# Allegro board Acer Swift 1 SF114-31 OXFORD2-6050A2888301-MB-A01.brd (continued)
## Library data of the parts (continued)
C13 C7111 C7116 C7125 = CSC0402: part number: CSC0402-CSC0402_DY,CSC0402_DY,CSC_100X050X040_2,0.55MM,CSC0402,0402,,CSC0402_OPEN; signal model: C2_CSC0402_DY_CSC0402_DY; room: Sheet14
C14 C4504 C4505 = CSC0402: part number: CSC0402-0.1UF_16V_2,6010A0036403,CSC_100X050X040_2,0.55MM,CSC0402,0402,X7R,CAP-CHIP,0.1UF,16V,K,X7R,0402,TAP; signal model: C2_6010A0036403_0_1uF_16V_2; room: Sheet37
C18 = CSC0402: part number: CSC0402-22PF_50V_2,6010072202AT,CSC_100X050X040_2,0.55MM,CSC0402,0402,C0G,CAPACITOR-CHIP,22PF,50V,J,C0G,0402,TR; signal model: C2_6010072202AT_22pF_50V_2; room: Sheet18
C300-C306 C316 = CSC0402: part number: CSC0402-0.1UF_16V_2,6010A0036403,CSC_100X050X040_2,0.55MM,CSC0402,0402,X7R,CAP-CHIP,0.1UF,16V,K,X7R,0402,TAP; signal model: C2_6010A0036403_0_1uF_16V_2; room: Sheet17
C310 = CSC0402: part number: CSC0402-1UF_6.3V_2,6010B0006001,CSC_100X050X040_2,0.55MM,CSC0402,0402,X5R,CAP-CHIP,1UF,6.3V,K,X5R,0402,TR; signal model: C2_6010B0006001_1uF_6_3V_2; room: Sheet17
C312 = CSC0603: part number: CSC0603-10UF_6.3V_3_DY,6010B0044901_DY,CSC_160X080X080_2,0.95MM,CSC0603,0603,X5R,CAP-CHIP,10UF,6.3V,M,X5R,0603,TR; signal model: C2_6010B0044901_DY_10uF_6_3V_3_DY; room: Sheet17
C313 = CSC0603: part number: CSC0603-4.7UF_6.3V_3,6010B0009904,CSC_160X080X080_2,0.95MM,CSC0603,0603,X5R,CAP-CHIP,4.7UF,6.3V,K,X5R,0603,TR; signal model: C2_6010B0009904_4_7uF_6_3V_3; room: Sheet17
C351 = CSC0402: part number: CSC0402-CSC0402_DY,CSC0402_DY,CSC_100X050X040_2,0.55MM,CSC0402,0402,,CSC0402_OPEN; signal model: C2_CSC0402_DY_CSC0402_DY; room: Sheet17
C501 C508 C512 C513 C515 C517 C521 C530 C532 = CSC0603: part number: CSC0603-10UF_6.3V_3,6010B0044901,CSC_160X080X080_2,0.95MM,CSC0603,0603,X5R,CAP-CHIP,10UF,6.3V,M,X5R,0603,TR; signal model: C2_6010B0044901_10uF_6_3V_3; room: Sheet18
C502 = CSC0402: part number: CSC0402-2.2UF_6.3V_2,6010B0059301,CSC_100X050X040_2,0.55MM,CSC0402,0402,X5R,CAP-CHIP,2.2UF,6.3V,M,X5R,0402,TR; signal model: C2_6010B0059301_2_2uF_6_3V_2; room: Sheet18
C503 C511 = CSC0402: part number: CSC0402-1UF_6.3V_2,6010B0006001,CSC_100X050X040_2,0.55MM,CSC0402,0402,X5R,CAP-CHIP,1UF,6.3V,K,X5R,0402,TR; signal model: C2_6010B0006001_1uF_6_3V_2; room: Sheet18
C504 = CSC0603: part number: CSC0603-4.7UF_10V_3,6010B0067401,CSC_160X080X080_2,0.95MM,CSC0603,0603,X5R,CAP-CHIP,4.7UF,10V,K,X5R,0603,TR; signal model: C2_6010B0067401_4_7uF_10V_3; room: Sheet18
C505 C507 C509 C514 C516 C520 = CSC0402: part number: CSC0402-0.1UF_16V_2,6010A0036403,CSC_100X050X040_2,0.55MM,CSC0402,0402,X7R,CAP-CHIP,0.1UF,16V,K,X7R,0402,TAP; signal model: C2_6010A0036403_0_1uF_16V_2; room: Sheet18
C506 C523-C525 = CSC0402: part number: CSC0402-CSC0402_DY,CSC0402_DY,CSC_100X050X040_2,0.55MM,CSC0402,0402,,CSC0402_OPEN; signal model: C2_CSC0402_DY_CSC0402_DY; room: Sheet18
C510 = CSC0402: part number: CSC0402-22PF_50V_2_DY,6010072202AT_DY,CSC_100X050X040_2,0.55MM,CSC0402,0402,C0G,CAPACITOR-CHIP,22PF,50V,J,C0G,0402,TR; signal model: C2_6010072202AT_DY_22pF_50V_2_DY; room: Sheet18
C519 = CSC0402: part number: CSC0402-0.1UF_16V_2_DY,6010A0036403_DY,CSC_100X050X040_2,0.55MM,CSC0402,0402,X7R,CAP-CHIP,0.1UF,16V,K,X7R,0402,TAP; signal model: C2_6010A0036403_DY_0_1uF_16V_2_DY; room: Sheet18
C522 = CSC0603: part number: CSC0603-10UF_6.3V_3_DY,6010B0044901_DY,CSC_160X080X080_2,0.95MM,CSC0603,0603,X5R,CAP-CHIP,10UF,6.3V,M,X5R,0603,TR; signal model: C2_6010B0044901_DY_10uF_6_3V_3_DY; room: Sheet18
C531 = CSC0603: part number: CSC0603-4.7UF_6.3V_3,6010B0009904,CSC_160X080X080_2,0.95MM,CSC0603,0603,X5R,CAP-CHIP,4.7UF,6.3V,K,X5R,0603,TR; signal model: C2_6010B0009904_4_7uF_6_3V_3; room: Sheet18
C600 C601 = CSC0402: part number: CSC0402-470PF_50V_2_DY,6010A0025101_DY,CSC_100X050X040_2,0.55MM,CSC0402,0402,X7R,CAP-CHIP-471-K,50V-X7R-0402-TAP; signal model: C2_6010A0025101_DY_470pF_50V_2_DY; room: Sheet19
C602 C603 = CSC0603: part number: CSC0603-4.7UF_6.3V_3,6010B0009904,CSC_160X080X080_2,0.95MM,CSC0603,0603,X5R,CAP-CHIP,4.7UF,6.3V,K,X5R,0603,TR; signal model: C2_6010B0009904_4_7uF_6_3V_3; room: Sheet19
C604-C611 = CSC0402: part number: CSC0402-CSC0402_DY,CSC0402_DY,CSC_100X050X040_2,0.55MM,CSC0402,0402,,CSC0402_OPEN; signal model: C2_CSC0402_DY_CSC0402_DY; room: Sheet19
C900 C905 = CSC0603: part number: CSC0603-4.7UF_6.3V_3,6010B0009904,CSC_160X080X080_2,0.95MM,CSC0603,0603,X5R,CAP-CHIP,4.7UF,6.3V,K,X5R,0603,TR; signal model: C2_6010B0009904_4_7uF_6_3V_3; room: Sheet20
C901 C904 = CSC0402: part number: CSC0402-1UF_6.3V_2,6010B0006001,CSC_100X050X040_2,0.55MM,CSC0402,0402,X5R,CAP-CHIP,1UF,6.3V,K,X5R,0402,TR; signal model: C2_6010B0006001_1uF_6_3V_2; room: Sheet20
C902 = CSC0402: part number: CSC0402-0.1UF_16V_2_DY,6010A0036403_DY,CSC_100X050X040_2,0.55MM,CSC0402,0402,X7R,CAP-CHIP,0.1UF,16V,K,X7R,0402,TAP; signal model: C2_6010A0036403_DY_0_1uF_16V_2_DY; room: Sheet20
C903 C906 = CSC0402: part number: CSC0402-0.1UF_16V_2,6010A0036403,CSC_100X050X040_2,0.55MM,CSC0402,0402,X7R,CAP-CHIP,0.1UF,16V,K,X7R,0402,TAP; signal model: C2_6010A0036403_0_1uF_16V_2; room: Sheet20
C907 = CSC0402: part number: CSC0402-6.8PF_50V_2_DY,6010B0047803_DY,CSC_100X050X030_2,0.45MM,CSC0402,0402,C0G,CAPACITOR-CHIP,6.8PF,50V,D,C0G,0402,TR; signal model: C2_6010B0047803_6_8PF_50V_2_DY; room: Sheet20
C1301 C1303 = CSC0603: part number: CSC0603-10UF_6.3V_3,6010B0044901,CSC_160X080X080_2,0.95MM,CSC0603,0603,X5R,CAP-CHIP,10UF,6.3V,M,X5R,0603,TR; signal model: C2_6010B0044901_10uF_6_3V_3; room: Sheet21
C1302 C1304 = CSC0402: part number: CSC0402-0.1UF_16V_2,6010A0036403,CSC_100X050X040_2,0.55MM,CSC0402,0402,X7R,CAP-CHIP,0.1UF,16V,K,X7R,0402,TAP; signal model: C2_6010A0036403_0_1uF_16V_2; room: Sheet21
C1305-C1307 = CSC0402: part number: CSC0402-CSC0402_DY,CSC0402_DY,CSC_100X050X040_2,0.55MM,CSC0402,0402,,CSC0402_OPEN; signal model: C2_CSC0402_DY_CSC0402_DY; room: Sheet21
C2000 = CSC0805: part number: CSC0805-22UF_6.3V_5_DY,6010A0040702_DY,CSC_200X125X130_2,1.45MM,CSC0805,0805,X5R,CAP-CHIP-22UF-6.3V-M-X5R-0805-TAP; signal model: C2_6010A0040702_DY_22uF_6_3V_5_DY; room: Sheet22
C2001 = CSC0603: part number: CSC0603-2.2UF_6.3V_3,6010B0027401,CSC_160X080X090_2,1.05MM,CSC0603,0603,X5R,CAPACITOR-CHIP,2.2UF,6.3V,K,X5R,0603,TR; signal model: C2_6010B0027401_2_2uF_6_3V_3; room: Sheet22
C2002 = CSC0805: part number: CSC0805-22UF_6.3V_5,6010A0040702,CSC_200X125X130_2,1.45MM,CSC0805,0805,X5R,CAP-CHIP-22UF-6.3V-M-X5R-0805-TAP; signal model: C2_6010A0040702_22uF_6_3V_5; room: Sheet22
C2003 = CSC0402: part number: CSC0402-0.1UF_16V_2,6010A0036403,CSC_100X050X040_2,0.55MM,CSC0402,0402,X7R,CAP-CHIP,0.1UF,16V,K,X7R,0402,TAP; signal model: C2_6010A0036403_0_1uF_16V_2; room: Sheet22
C2004 = CSC0402: part number: CSC0402-CSC0402_DY,CSC0402_DY,CSC_100X050X040_2,0.55MM,CSC0402,0402,,CSC0402_OPEN; signal model: C2_CSC0402_DY_CSC0402_DY; room: Sheet22
C2005 = CAP_TANT: part number: CAP_TANT-100UF_6.3V_DY,6010A0052401_DY,CSTJB2_362X305X190_2,2.05MM,CAP_TANT,,,CAPACITOR-TANT-100UF-6.3V-M-85C-B2-ULESR-TAP; signal model: C2_6010A0052401_100uF_6_3V_DY; room: Sheet22
C2007 = CSC0805: part number: CSC0805-22UF_6.3V_5,6010A0040702,CSC_200X125X130_2,1.45MM,CSC0805,0805,X5R,CAP-CHIP-22UF-6.3V-M-X5R-0805-TAP; signal model: C2_6010A0040702_22uF_6_3V_5; room: Sheet47
C2426 = CSC0805: part number: CSC0805-22UF_6.3V_5,6010A0040702,CSC_200X125X130_2,1.45MM,CSC0805,0805,X5R,CAP-CHIP-22UF-6.3V-M-X5R-0805-TAP; signal model: C2_6010A0040702_22uF_6_3V_5; room: Sheet23
C2427 C2440 C2441 = CSC0402: part number: CSC0402-0.1UF_16V_2,6010A0036403,CSC_100X050X040_2,0.55MM,CSC0402,0402,X7R,CAP-CHIP,0.1UF,16V,K,X7R,0402,TAP; signal model: C2_6010A0036403_0_1uF_16V_2; room: Sheet23
C2428 = CAP_TANT: part number: CAP_TANT-100UF_6.3V_DY,6010A0052401_DY,CSTJB2_362X305X190_2,2.05MM,CAP_TANT,,,CAPACITOR-TANT-100UF-6.3V-M-85C-B2-ULESR-TAP; signal model: C2_6010A0052401_100uF_6_3V_DY; room: Sheet23
C2432 = CSC0402: part number: CSC0402-1000PF_50V_2,6010071020AT,CSC_100X050X055_2,0.7MM,CSC0402,0402,X7R,CAPACITOR-CHIP,1000PF,50V,K,X7R,0402,TR; signal model: C2_6010071020AT_1000PF_50V_2; room: Sheet23
C2456 = CSC0603: part number: CSC0603-2.2UF_6.3V_3,6010B0027401,CSC_160X080X090_2,1.05MM,CSC0603,0603,X5R,CAPACITOR-CHIP,2.2UF,6.3V,K,X5R,0603,TR; signal model: C2_6010B0027401_2_2uF_6_3V_3; room: Sheet23
C2457 = CSC0805: part number: CSC0805-47UF_6.3V_5_DY,6010B0096601_DY,CSC_200X125X130_2,1.45MM,CSC0805,0805,X5R,CAP-CHIP,47UF,6.3V,M,X5R,0805,TR; signal model: C2_6010B0096601_DY_47uF_6_3V_5_DY; room: Sheet23
C2460 C2462 = CSC0402: part number: CSC0402-0.1UF_16V_2,6010A0036403,CSC_100X050X040_2,0.55MM,CSC0402,0402,X7R,CAP-CHIP,0.1UF,16V,K,X7R,0402,TAP; signal model: C2_6010A0036403_0_1uF_16V_2; room: Sheet47
C2461 = CSC0402: part number: CSC0402-1000PF_50V_2,6010071020AT,CSC_100X050X055_2,0.7MM,CSC0402,0402,X7R,CAPACITOR-CHIP,1000PF,50V,K,X7R,0402,TR; signal model: C2_6010071020AT_1000PF_50V_2; room: Sheet47
C3000 = CSC0402: part number: CSC0402-0.01UF_50V_2,6010B0058401,CSC_100X050X040_2,0.55MM,CSC0402,0402,X7R,CAP-CHIP,0.01UF,50V,K,X7R,0402,TAP; signal model: C2_6010B0058401_0_01uF_50V_2; room: Sheet26
C3001 C3014 = CSC0402: part number: CSC0402-0.1UF_16V_2,6010A0036403,CSC_100X050X040_2,0.55MM,CSC0402,0402,X7R,CAP-CHIP,0.1UF,16V,K,X7R,0402,TAP; signal model: C2_6010A0036403_0_1uF_16V_2; room: Sheet26
C3002 = CSC0603: part number: CSC0603-10UF_6.3V_3,6010B0044901,CSC_160X080X080_2,0.95MM,CSC0603,0603,X5R,CAP-CHIP,10UF,6.3V,M,X5R,0603,TR; signal model: C2_6010B0044901_10uF_6_3V_3; room: Sheet26
C3003 = CSC0402: part number: CSC0402-680PF_50V_2,6010A0025501,CSC_100X050X040_2,0.55MM,CSC0402,0402,X7R,CAP-CHIP-681-K,50V-X7R-0402-TAP; signal model: C2_6010A0025501_680pF_50V_2; room: Sheet26
C3007 C3016 = CSC0402: part number: CSC0402-CSC0402_DY,CSC0402_DY,CSC_100X050X040_2,0.55MM,CSC0402,0402,,CSC0402_OPEN; signal model: C2_CSC0402_DY_CSC0402_DY; room: Sheet26
C3008 = CSC0402: part number: CSC0402-1000PF_50V_2,6010071020AT,CSC_100X050X055_2,0.7MM,CSC0402,0402,X7R,CAPACITOR-CHIP,1000PF,50V,K,X7R,0402,TR; signal model: C2_6010071020AT_1000PF_50V_2; room: Sheet26
C3009 = CSC0402: part number: CSC0402-0.1UF_16V_2_DY,6010A0036403_DY,CSC_100X050X040_2,0.55MM,CSC0402,0402,X7R,CAP-CHIP,0.1UF,16V,K,X7R,0402,TAP; signal model: C2_6010A0036403_DY_0_1uF_16V_2_DY; room: Sheet26
C3010 C3011 C4611-C4614 = CSC0402: part number: CSC0402-0.1UF_16V_2,6010A0036403,CSC_100X050X040_2,0.55MM,CSC0402,0402,X7R,CAP-CHIP,0.1UF,16V,K,X7R,0402,TAP; signal model: C2_6010A0036403_0_1uF_16V_2; room: Sheet36
C3015 = CSC0402: part number: CSC0402-0.047UF_16V_2_DY,6010B0046101_DY,CSC_100X050X040_2,0.55MM,CSC0402,0402,X7R,CAP-CHIP,0.047UF,16V,K,X7R,0402,TAP; signal model: C2_6010B0046101_0_047uF_16V_2_DY; room: Sheet26
C3019 = CSC0603: part number: CSC0603-4.7UF_25V_3,6010B0322201,CSC_160X080X095_2,1.10MM,CSC0603,0603,,CAPACITOR-CHIP,4.7UF,25V,K,X5R,0603,TR,0.8MM; signal model: C2_6010B0322201_4_7uF_25V_3; room: Sheet26
C3020 = CSC0402: part number: CSC0402-0.1UF_25V_2,6010B0087101,CSC_100X050X040_2,0.55MM,CSC0402,0402,X5R,CAP-CHIP,0.1UF,25V,K,X5R,0402,TR; signal model: C2_6010B0087101_0_1uF_25V_2; room: Sheet26
C3150 = CSC0402: part number: CSC0402-100PF_50V_2,6010071012AT,CSC_100X050X040_2,0.55MM,CSC0402,0402,NPO,CAP-CHIP-101-J,50V-NPO-0402; signal model: C2_6010071012AT_100pF_50V_2; room: Sheet27
C3151 = CSC0402: part number: CSC0402-22PF_50V_2_DY,6010072202AT_DY,CSC_100X050X040_2,0.55MM,CSC0402,0402,C0G,CAPACITOR-CHIP,22PF,50V,J,C0G,0402,TR; signal model: C2_6010072202AT_DY_22pF_50V_2_DY; room: Sheet27
C3160-C3167 = CSC0402: part number: CSC0402-0.1UF_16V_2,6010A0036403,CSC_100X050X040_2,0.55MM,CSC0402,0402,X7R,CAP-CHIP,0.1UF,16V,K,X7R,0402,TAP; signal model: C2_6010A0036403_0_1uF_16V_2; room: Sheet27
C3500 C3505 = CSC0603: part number: CSC0603-4.7UF_6.3V_3_DY,6010B0009904_DY,CSC_160X080X080_2,0.95MM,CSC0603,0603,X5R,CAP-CHIP,4.7UF,6.3V,K,X5R,0603,TR; signal model: C2_6010B0009904_DY_4_7uF_6_3V_3_DY; room: Sheet25
C3501-C3504 = CSC0402: part number: CSC0402-0.1UF_16V_2_DY,6010A0036403_DY,CSC_100X050X040_2,0.55MM,CSC0402,0402,X7R,CAP-CHIP,0.1UF,16V,K,X7R,0402,TAP; signal model: C2_6010A0036403_DY_0_1uF_16V_2_DY; room: Sheet25
C3950 C3951 C3954 C3955 = CSC0402: part number: CSC0402-2.2UF_6.3V_2,6010B0059301,CSC_100X050X040_2,0.55MM,CSC0402,0402,X5R,CAP-CHIP,2.2UF,6.3V,M,X5R,0402,TR; signal model: C2_6010B0059301_2_2uF_6_3V_2; room: Sheet24
C3952 C3953 C3956 C3957 C3959 = CSC0402: part number: CSC0402-0.1UF_16V_2,6010A0036403,CSC_100X050X040_2,0.55MM,CSC0402,0402,X7R,CAP-CHIP,0.1UF,16V,K,X7R,0402,TAP; signal model: C2_6010A0036403_0_1uF_16V_2; room: Sheet24
C3958 = CSC0402: part number: CSC0402-CSC0402_DY,CSC0402_DY,CSC_100X050X040_2,0.55MM,CSC0402,0402,,CSC0402_OPEN; signal model: C2_CSC0402_DY_CSC0402_DY; room: Sheet24
C3960 = CSC0402: part number: CSC0402-12PF_50V_2,6010A0036103,CSC_100X050X040_2,0.55MM,CSC0402,0402,NPO,CAP-CHIP-12PF-50V-J-NPO-0402-TAP; signal model: C2_6010A0036103_12pF_50V_2; room: Sheet24
C4100 C4101 C4107 C4143 C4144 C4150 C4151 C4158-C4160 = CSC0402: part number: CSC0402-0.22UF_6.3V_2,6010A0050701,CSC_100X050X040_2,0.55MM,CSC0402,0402,X5R,CAP-CHIP-0.22UF-M-6.3V-X5R-0402-TAP; signal model: C2_6010A0050701_0_22uF_6_3V_2; room: Sheet30
C4102 C4441 = CSC0402: part number: CSC0402-0.1UF_16V_2,6010A0036403,CSC_100X050X040_2,0.55MM,CSC0402,0402,X7R,CAP-CHIP,0.1UF,16V,K,X7R,0402,TAP; signal model: C2_6010A0036403_0_1uF_16V_2; room: Sheet30
C4103 C4110-C4112 C4251 C4252 = CSC0402: part number: CSC0402-0.1UF_16V_2,6010A0036403,CSC_100X050X040_2,0.55MM,CSC0402,0402,X7R,CAP-CHIP,0.1UF,16V,K,X7R,0402,TAP; signal model: C2_6010A0036403_0_1uF_16V_2; room: Sheet28
C4104-C4106 C4108 C4109 C4117-C4131 = CSC0402: part number: CSC0402-0.22UF_6.3V_2,6010A0050701,CSC_100X050X040_2,0.55MM,CSC0402,0402,X5R,CAP-CHIP-0.22UF-M-6.3V-X5R-0402-TAP; signal model: C2_6010A0050701_0_22uF_6_3V_2; room: Sheet28
C4113-C4116 = CSC0402: part number: CSC0402-0.1UF_16V_2,6010A0036403,CSC_100X050X040_2,0.55MM,CSC0402,0402,X7R,CAP-CHIP,0.1UF,16V,K,X7R,0402,TAP; signal model: C2_6010A0036403_0_1uF_16V_2; room: Sheet29
C4132 = CSC0402: part number: CSC0402-180PF_50V_2,6010B0045801,CSC_100X050X055_2,0.7MM,CSC0402,0402,NP0,CAPACITOR-CHIP,180PF,50V,J,NP0,0402,TR; signal model: C2_6010B0045801_180pF_50V_2; room: Sheet28
C4133-C4142 C4145-C4149 C4152-C4155 C4157 = CSC0402: part number: CSC0402-0.22UF_6.3V_2,6010A0050701,CSC_100X050X040_2,0.55MM,CSC0402,0402,X5R,CAP-CHIP-0.22UF-M-6.3V-X5R-0402-TAP; signal model: C2_6010A0050701_0_22uF_6_3V_2; room: Sheet29
C4156 = CSC0402: part number: CSC0402-180PF_50V_2,6010B0045801,CSC_100X050X055_2,0.7MM,CSC0402,0402,NP0,CAPACITOR-CHIP,180PF,50V,J,NP0,0402,TR; signal model: C2_6010B0045801_180pF_50V_2; room: Sheet29
C4163-C4167 C4169 = CSC0402: part number: CSC0402-0.1UF_10V_2,6010A0010501,CSC_100X050X040_2,0.55MM,CSC0402,0402,X7R,CAP-CHIP-104-J,10V-X7R-0402-TAP; signal model: C2_6010A0010501_0_1uF_10V_2; room: Sheet31
C4168 C4170-C4188 = CSC0402: part number: CSC0402-0.22UF_6.3V_2,6010A0050701,CSC_100X050X040_2,0.55MM,CSC0402,0402,X5R,CAP-CHIP-0.22UF-M-6.3V-X5R-0402-TAP; signal model: C2_6010A0050701_0_22uF_6_3V_2; room: Sheet31
C4189 = CSC0402: part number: CSC0402-180PF_50V_2,6010B0045801,CSC_100X050X055_2,0.7MM,CSC0402,0402,NP0,CAPACITOR-CHIP,180PF,50V,J,NP0,0402,TR; signal model: C2_6010B0045801_180pF_50V_2; room: Sheet31
C4190-C4193 = CSC0402: part number: CSC0402-0.1UF_10V_2,6010A0010501,CSC_100X050X040_2,0.55MM,CSC0402,0402,X7R,CAP-CHIP-104-J,10V-X7R-0402-TAP; signal model: C2_6010A0010501_0_1uF_10V_2; room: Sheet32
C4194-C4199 C4201-C4214 = CSC0402: part number: CSC0402-0.22UF_6.3V_2,6010A0050701,CSC_100X050X040_2,0.55MM,CSC0402,0402,X5R,CAP-CHIP-0.22UF-M-6.3V-X5R-0402-TAP; signal model: C2_6010A0050701_0_22uF_6_3V_2; room: Sheet32
C4200 = CSC0402: part number: CSC0402-0.1UF_10V_2,6010A0010501,CSC_100X050X040_2,0.55MM,CSC0402,0402,X7R,CAP-CHIP-104-J,10V-X7R-0402-TAP; signal model: C2_6010A0010501_0_1uF_10V_2; room: Sheet33
C4215 = CSC0402: part number: CSC0402-180PF_50V_2,6010B0045801,CSC_100X050X055_2,0.7MM,CSC0402,0402,NP0,CAPACITOR-CHIP,180PF,50V,J,NP0,0402,TR; signal model: C2_6010B0045801_180pF_50V_2; room: Sheet32
C4506 C4507 = CSC0402: part number: CSC0402-0.1UF_16V_2_DY,6010A0036403_DY,CSC_100X050X040_2,0.55MM,CSC0402,0402,X7R,CAP-CHIP,0.1UF,16V,K,X7R,0402,TAP; signal model: C2_6010A0036403_DY_0_1uF_16V_2_DY; room: Sheet38
C4509 C4510 = CSC0402: part number: CSC0402-12PF_50V_2,6010A0036103,CSC_100X050X040_2,0.55MM,CSC0402,0402,NPO,CAP-CHIP-12PF-50V-J-NPO-0402-TAP; signal model: C2_6010A0036103_12pF_50V_2; room: Sheet38
C4511 C4512 = CSC0402: part number: CSC0402-15PF_50V_2,6010071502AT,CSC_100X050X040_2,0.55MM,CSC0402,0402,NPO,CAP-CHIP,15PF,J-50V-NPO-0402-TAP; signal model: C2_6010071502AT_15pF_50V_2; room: Sheet40
C4513 = CSC0402: part number: CSC0402-0.1UF_16V_2,6010A0036403,CSC_100X050X040_2,0.55MM,CSC0402,0402,X7R,CAP-CHIP,0.1UF,16V,K,X7R,0402,TAP; signal model: C2_6010A0036403_0_1uF_16V_2; room: Sheet40
C4514 C4625 = CSC0402: part number: CSC0402-1UF_10V_2,6010B0055001,CSC_100X050X040_2,0.55MM,CSC0402,0402,X5R,CAP-CHIP,1UF,10V,K,X5R,0402,TR; signal model: C2_6010B0055001_1uF_10V_2; room: Sheet40
C4515 = CSC0402: part number: CSC0402-0.1UF_16V_2_DY,6010A0036403_DY,CSC_100X050X040_2,0.55MM,CSC0402,0402,X7R,CAP-CHIP,0.1UF,16V,K,X7R,0402,TAP; signal model: C2_6010A0036403_DY_0_1uF_16V_2_DY; room: Sheet40
C4516 C4525 C4526 C4564 C4565 C4609 C4630 = CSC0805: part number: CSC0805-22UF_6.3V_5,6010A0040702,CSC_200X125X130_2,1.45MM,CSC0805,0805,X5R,CAP-CHIP-22UF-6.3V-M-X5R-0805-TAP; signal model: C2_6010A0040702_22uF_6_3V_5; room: Sheet41
C4517-C4524 C4527-C4531 C4555 C4566 = CSC0402: part number: CSC0402-2.2UF_6.3V_2,6010B0059301,CSC_100X050X040_2,0.55MM,CSC0402,0402,X5R,CAP-CHIP,2.2UF,6.3V,M,X5R,0402,TR; signal model: C2_6010B0059301_2_2uF_6_3V_2; room: Sheet41
C4532-C4545 C4548-C4553 C4556-C4563 C4569 C4570 C4626 = CSC0402: part number: CSC0402-1UF_6.3V_2,6010B0006001,CSC_100X050X040_2,0.55MM,CSC0402,0402,X5R,CAP-CHIP,1UF,6.3V,K,X5R,0402,TR; signal model: C2_6010B0006001_1uF_6_3V_2; room: Sheet41
C4546 C4547 C4554 C4640 = CSC0603: part number: CSC0603-22UF_6.3V_3,6010B0219001,CSC_160X080X090_2,1.05MM,CSC0603,0603,,CAPACITOR-CHIP,22UF,6.3V,R6,0603,TR; signal model: C2_6010B0219001_22UF_6_3V_3; room: Sheet41
C4571 C4573 C4579-C4608 = CSC0402: part number: CSC0402-1UF_6.3V_2,6010B0006001,CSC_100X050X040_2,0.55MM,CSC0402,0402,X5R,CAP-CHIP,1UF,6.3V,K,X5R,0402,TR; signal model: C2_6010B0006001_1uF_6_3V_2; room: Sheet42
C4572 C4574-C4578 = CSC0603: part number: CSC0603-22UF_6.3V_3,6010B0219001,CSC_160X080X090_2,1.05MM,CSC0603,0603,,CAPACITOR-CHIP,22UF,6.3V,R6,0603,TR; signal model: C2_6010B0219001_22UF_6_3V_3; room: Sheet42
C4610 = CSC0402: part number: CSC0402-0.1UF_10V_2_DY,6010A0010501_DY,CSC_100X050X040_2,0.55MM,CSC0402,0402,X7R,CAP-CHIP-104-J,10V-X7R-0402-TAP; signal model: C2_6010A0010501_DY_0_1uF_10V_2_DY; room: Sheet35
C4616 = CSC0402: part number: CSC0402-0.2PF_50V_2,6010B0263501,CSC_100X050X055_2,0.70MM,CSC0402,0402,NP0,CAPACITOR-CHIP,0.2PF,50V,B,NP0,0402,TR; signal model: C2_6010B0263501_0_2pF_50V_2; room: Sheet34
C4617 = CSC0402: part number: CSC0402-0.1UF_10V_2_DY,6010A0010501_DY,CSC_100X050X040_2,0.55MM,CSC0402,0402,X7R,CAP-CHIP-104-J,10V-X7R-0402-TAP; signal model: C2_6010A0010501_DY_0_1uF_10V_2_DY; room: Sheet34
C4623 = CSC0402: part number: CSC0402-0.2PF_50V_2,6010B0263501,CSC_100X050X055_2,0.70MM,CSC0402,0402,NP0,CAPACITOR-CHIP,0.2PF,50V,B,NP0,0402,TR; signal model: C2_6010B0263501_0_2pF_50V_2; room: Sheet35
C4627 = CSC0805: part number: CSC0805-CSC0805_DY,CSC0805_DY,CSC_200X125X130_2,1.45MM,CSC0805,0805,,CSC0805_OPEN; signal model: C2_CSC0805_DY_CSC0805_DY; room: Sheet40
C4631 C4636 = CSC0402: part number: CSC0402-0.1UF_16V_2,6010A0036403,CSC_100X050X040_2,0.55MM,CSC0402,0402,X7R,CAP-CHIP,0.1UF,16V,K,X7R,0402,TAP; signal model: C2_6010A0036403_0_1uF_16V_2; room: Sheet38
C4652 = CSC0402: part number: CSC0402-CSC0402_DY,CSC0402_DY,CSC_100X050X040_2,0.55MM,CSC0402,0402,,CSC0402_OPEN; signal model: C2_CSC0402_DY_CSC0402_DY; room: Sheet37
C6000 C6010 = CSC0805: part number: CSC0805-10UF_25V_5,6010B0150801,CSC_200X125X140_2,1.55MM,CSC0805,0805,X5R,CAP-CHIP,10UF,25V,K,X5R,0805,TR,1.25MM; signal model: C2_6010B0150801_10UF_25V_5; room: Sheet5
C6001 C6011 = CSC0805: part number: CSC0805-4.7UF_25V_5,6010B0048901,CSC_200X125X130_2,1.45MM,CSC0805,0805,X5R,CAP-CHIP,4.7UF,25V,K,X5R,0805,TR; signal model: C2_6010B0048901_4_7uF_25V_5; room: Sheet5
C6020 C6023 C6032 = CSC0402: part number: CSC0402-0.1UF_16V_2,6010A0036403,CSC_100X050X040_2,0.55MM,CSC0402,0402,X7R,CAP-CHIP,0.1UF,16V,K,X7R,0402,TAP; signal model: C2_6010A0036403_0_1uF_16V_2; room: Sheet5
C6021 C6022 C6024 C6025 C6031 = CSC0603: part number: CSC0603-0.1UF_25V_3,6010A0057701,CSC_160X080X080_2,0.95MM,CSC0603,0603,X7R,CAP-CHIP,0.1UF,25V,K,X7R,0603,TR; signal model: C2_6010A0057701_0_1uF_25V_3; room: Sheet5
C6026 = CSC0603: part number: CSC0603-1UF_25V_3,6010B0067601,CSC_160X080X080_2,0.95MM,CSC0603,0603,X5R,CAP-CHIP,1UF,25V,K,X5R,0603,TR; signal model: C2_6010B0067601_1uF_25V_3; room: Sheet5
C6027 = CSC0402: part number: CSC0402-0.047UF_16V_2,6010B0046101,CSC_100X050X040_2,0.55MM,CSC0402,0402,X7R,CAP-CHIP,0.047UF,16V,K,X7R,0402,TAP; signal model: C2_6010B0046101_0_047uF_16V_2; room: Sheet5
C6028 C6051 = CSC0402: part number: CSC0402-1UF_10V_2,6010B0055001,CSC_100X050X040_2,0.55MM,CSC0402,0402,X5R,CAP-CHIP,1UF,10V,K,X5R,0402,TR; signal model: C2_6010B0055001_1uF_10V_2; room: Sheet5
C6030 C7604 = CSC0402: part number: CSC0402-470PF_50V_2,6010A0025101,CSC_100X050X040_2,0.55MM,CSC0402,0402,X7R,CAP-CHIP-471-K,50V-X7R-0402-TAP; signal model: C2_6010A0025101_470pF_50V_2; room: Sheet5
C6033 = CSC0603: part number: CSC0603-0.1UF_25V_3_DY,6010A0057701_DY,CSC_160X080X080_2,0.95MM,CSC0603,0603,X7R,CAP-CHIP,0.1UF,25V,K,X7R,0603,TR; signal model: C2_6010A0057701_0_1uF_25V_3_DY; room: Sheet5
C6036 C6037 = CSC0402: part number: CSC0402-100PF_50V_2,6010071012AT,CSC_100X050X040_2,0.55MM,CSC0402,0402,NPO,CAP-CHIP-101-J,50V-NPO-0402; signal model: C2_6010071012AT_100pF_50V_2; room: Sheet5
C6050 C7601 = CSC0402: part number: CSC0402-1000PF_50V_2,6010071020AT,CSC_100X050X055_2,0.7MM,CSC0402,0402,X7R,CAPACITOR-CHIP,1000PF,50V,K,X7R,0402,TR; signal model: C2_6010071020AT_1000PF_50V_2; room: Sheet5
C6100 C6150 = CAP_AL_SP: part number: CAP_AL_SP-100UF_6.3V,6010B0228101,CS_730X430X210_2,2.25MM,CAP_AL_SP,,,CAPACITOR-AL-SP,100UF,6.3V,M,-40~+105C,DX1.9,SMD,TR,17MOHM; signal model: C2_6010B0228101_100uF_6_3V; room: Sheet6
C6109 C6115 C6165 C6169 = CSC0402: part number: CSC0402-0.1UF_16V_2,6010A0036403,CSC_100X050X040_2,0.55MM,CSC0402,0402,X7R,CAP-CHIP,0.1UF,16V,K,X7R,0402,TAP; signal model: C2_6010A0036403_0_1uF_16V_2; room: Sheet6
C6110 C6160 C6161 = CSC0805: part number: CSC0805-10UF_25V_5,6010B0150801,CSC_200X125X140_2,1.55MM,CSC0805,0805,X5R,CAP-CHIP,10UF,25V,K,X5R,0805,TR,1.25MM; signal model: C2_6010B0150801_10UF_25V_5; room: Sheet6
C6111 = CSC0805: part number: CSC0805-4.7UF_25V_5,6010B0048901,CSC_200X125X130_2,1.45MM,CSC0805,0805,X5R,CAP-CHIP,4.7UF,25V,K,X5R,0805,TR; signal model: C2_6010B0048901_4_7uF_25V_5; room: Sheet6
C6121 = CSC0603: part number: CSC0603-10UF_6.3V_3,6010B0044901,CSC_160X080X080_2,0.95MM,CSC0603,0603,X5R,CAP-CHIP,10UF,6.3V,M,X5R,0603,TR; signal model: C2_6010B0044901_10uF_6_3V_3; room: Sheet6
C6122 C6172 = CSC0402: part number: CSC0402-1UF_6.3V_2,6010B0006001,CSC_100X050X040_2,0.55MM,CSC0402,0402,X5R,CAP-CHIP,1UF,6.3V,K,X5R,0402,TR; signal model: C2_6010B0006001_1uF_6_3V_2; room: Sheet6
C6162 = CSC0805: part number: CSC0805-10UF_25V_5_DY,6010B0150801_DY,CSC_200X125X140_2,1.55MM,CSC0805,0805,X5R,CAP-CHIP,10UF,25V,K,X5R,0805,TR,1.25MM; signal model: C2_6010B0150801_10UF_25V_5_DY; room: Sheet6
C6166 = CSC0402: part number: CSC0402-CSC0402_DY,CSC0402_DY,CSC_100X050X040_2,0.55MM,CSC0402,0402,,CSC0402_OPEN; signal model: C2_CSC0402_DY_CSC0402_DY; room: Sheet6
C6600-C6608 = CSC0805: part number: CSC0805-22UF_6.3V_5,6010A0040702,CSC_200X125X130_2,1.45MM,CSC0805,0805,X5R,CAP-CHIP-22UF-6.3V-M-X5R-0805-TAP; signal model: C2_6010A0040702_22uF_6_3V_5; room: Sheet9
C6609 = CAP_AL_SP: part number: CAP_AL_SP-220UF_2V_10%,6010B0216001,CS_730X430X210_2,2.25MM,CAP_AL_SP,,,CAPACITOR-AL-SP,220UF,2V,-35%/+10%,105C,DX1.9,SMD,TR,9MOHM; signal model: C2_6010B0216001_220uF_2V_10%; room: Sheet9
C6610 C6611 = CSC0805: part number: CSC0805-10UF_25V_5,6010B0150801,CSC_200X125X140_2,1.55MM,CSC0805,0805,X5R,CAP-CHIP,10UF,25V,K,X5R,0805,TR,1.25MM; signal model: C2_6010B0150801_10UF_25V_5; room: Sheet9
C6612 = CSC0402: part number: CSC0402-0.1UF_25V_2,6010B0087101,CSC_100X050X040_2,0.55MM,CSC0402,0402,X5R,CAP-CHIP,0.1UF,25V,K,X5R,0402,TR; signal model: C2_6010B0087101_0_1uF_25V_2; room: Sheet9
C6613 = CSC0402: part number: CSC0402-330PF_50V_2,6010A0010301,CSC_100X050X040_2,0.55MM,CSC0402,0402,X7R,CAP-CHIP-331-J,50V-X7R-0402-TAP; signal model: C2_6010A0010301_330pF_50V_2; room: Sheet8
C6614 = CSC0402: part number: CSC0402-10PF_50V_2,6010A0025401,CSC_100X050X040_2,0.55MM,CSC0402,0402,NPO,CAP-CHIP-10PF-D,50V-NPO-0402-TAP; signal model: C2_6010A0025401_10pF_50V_2; room: Sheet8
C6615 = CSC0402: part number: CSC0402-0.22UF_16V_2,6010B0150901,CSC_100X050X055_2,0.7MM,CSC0402,0402,X7R,CAPACITOR-CHIP,0.22UF,16V,K,X7R,0402,TR,0.5MM; signal model: C2_6010B0150901_0_22uF_16V_2; room: Sheet8
C6616 C6618 = CSC0402: part number: CSC0402-1000PF_50V_2,6010071020AT,CSC_100X050X055_2,0.7MM,CSC0402,0402,X7R,CAPACITOR-CHIP,1000PF,50V,K,X7R,0402,TR; signal model: C2_6010071020AT_1000PF_50V_2; room: Sheet8
C6617 = CSC0402: part number: CSC0402-4700PF_50V_2,6010A0029301,CSC_100X050X040_2,0.55MM,CSC0402,0402,X7R,CAP-CHIP-472-K,50V-X7R-0402-TAP; signal model: C2_6010A0029301_4700pF_50V_2; room: Sheet8
C6639 = CSC0402: part number: CSC0402-CSC0402_DY,CSC0402_DY,CSC_100X050X040_2,0.55MM,CSC0402,0402,,CSC0402_OPEN; signal model: C2_CSC0402_DY_CSC0402_DY; room: Sheet8
C6640 = CSC0402: part number: CSC0402-1.2PF_50V_2,6010B0077201,CSC_100X050X040_2,0.55MM,CSC0402,0402,C0G,CAP-CHIP,1.2PF,50V,B,C0G,0402,TR; signal model: C2_6010B0077201_1_2pF_50V_2; room: Sheet8
C6642 = CSC0402: part number: CSC0402-1UF_6.3V_2,6010B0006001,CSC_100X050X040_2,0.55MM,CSC0402,0402,X5R,CAP-CHIP,1UF,6.3V,K,X5R,0402,TR; signal model: C2_6010B0006001_1uF_6_3V_2; room: Sheet8
C6643 = CSC0603: part number: CSC0603-2.2UF_6.3V_3,6010B0027401,CSC_160X080X090_2,1.05MM,CSC0603,0603,X5R,CAPACITOR-CHIP,2.2UF,6.3V,K,X5R,0603,TR; signal model: C2_6010B0027401_2_2uF_6_3V_3; room: Sheet8
C6645 = CSC0402: part number: CSC0402-470PF_50V_2,6010A0025101,CSC_100X050X040_2,0.55MM,CSC0402,0402,X7R,CAP-CHIP-471-K,50V-X7R-0402-TAP; signal model: C2_6010A0025101_470pF_50V_2; room: Sheet8
C6646 C6647 = CSC0402: part number: CSC0402-0.01UF_50V_2,6010B0058401,CSC_100X050X040_2,0.55MM,CSC0402,0402,X7R,CAP-CHIP,0.01UF,50V,K,X7R,0402,TAP; signal model: C2_6010B0058401_0_01uF_50V_2; room: Sheet8
C6649 = CSC0402: part number: CSC0402-2200PF_50V_2,6010A0036305,CSC_100X050X040_2,0.55MM,CSC0402,0402,X7R,CAP-CHIP-2200PF-50V-K-X7R-0402-TAP; signal model: C2_6010A0036305_2200pF_50V_2; room: Sheet8
C6699 = CAP_AL_SP: part number: CAP_AL_SP-15UF_25V_DY,6010B0217801_DY,CS_730X430X210_2_615,2.25MM,CAP_AL_SP,,,CAPACITOR-AL-SP,15UF,25V,M,105C,DX1.9,TR,70MOHM; signal model: C2_6010B0217801_DY_15uF_25V_DY; room: Sheet9
C6700 C6701 = CSC0805: part number: CSC0805-22UF_6.3V_5,6010A0040702,CSC_200X125X130_2,1.45MM,CSC0805,0805,X5R,CAP-CHIP-22UF-6.3V-M-X5R-0805-TAP; signal model: C2_6010A0040702_22uF_6_3V_5; room: Sheet11
C6702 = CAP_AL_SP: part number: CAP_AL_SP-220UF_2V_10%,6010B0216001,CS_730X430X210_2,2.25MM,CAP_AL_SP,,,CAPACITOR-AL-SP,220UF,2V,-35%/+10%,105C,DX1.9,SMD,TR,9MOHM; signal model: C2_6010B0216001_220uF_2V_10%; room: Sheet11
C6710 C6711 = CSC0805: part number: CSC0805-10UF_25V_5,6010B0150801,CSC_200X125X140_2,1.55MM,CSC0805,0805,X5R,CAP-CHIP,10UF,25V,K,X5R,0805,TR,1.25MM; signal model: C2_6010B0150801_10UF_25V_5; room: Sheet11
C6712 = CSC0402: part number: CSC0402-0.1UF_25V_2,6010B0087101,CSC_100X050X040_2,0.55MM,CSC0402,0402,X5R,CAP-CHIP,0.1UF,25V,K,X5R,0402,TR; signal model: C2_6010B0087101_0_1uF_25V_2; room: Sheet11
C6713 = CSC0402: part number: CSC0402-330PF_50V_2,6010A0010301,CSC_100X050X040_2,0.55MM,CSC0402,0402,X7R,CAP-CHIP-331-J,50V-X7R-0402-TAP; signal model: C2_6010A0010301_330pF_50V_2; room: Sheet10
C6714 = CSC0402: part number: CSC0402-10PF_50V_2,6010A0025401,CSC_100X050X040_2,0.55MM,CSC0402,0402,NPO,CAP-CHIP-10PF-D,50V-NPO-0402-TAP; signal model: C2_6010A0025401_10pF_50V_2; room: Sheet10
C6715 = CSC0402: part number: CSC0402-0.22UF_16V_2,6010B0150901,CSC_100X050X055_2,0.7MM,CSC0402,0402,X7R,CAPACITOR-CHIP,0.22UF,16V,K,X7R,0402,TR,0.5MM; signal model: C2_6010B0150901_0_22uF_16V_2; room: Sheet10
C6716 C6718 = CSC0402: part number: CSC0402-1000PF_50V_2,6010071020AT,CSC_100X050X055_2,0.7MM,CSC0402,0402,X7R,CAPACITOR-CHIP,1000PF,50V,K,X7R,0402,TR; signal model: C2_6010071020AT_1000PF_50V_2; room: Sheet10
C6717 = CSC0402: part number: CSC0402-4700PF_50V_2,6010A0029301,CSC_100X050X040_2,0.55MM,CSC0402,0402,X7R,CAP-CHIP-472-K,50V-X7R-0402-TAP; signal model: C2_6010A0029301_4700pF_50V_2; room: Sheet10
C6739 = CSC0402: part number: CSC0402-CSC0402_DY,CSC0402_DY,CSC_100X050X040_2,0.55MM,CSC0402,0402,,CSC0402_OPEN; signal model: C2_CSC0402_DY_CSC0402_DY; room: Sheet10
C6740 = CSC0402: part number: CSC0402-1.2PF_50V_2,6010B0077201,CSC_100X050X040_2,0.55MM,CSC0402,0402,C0G,CAP-CHIP,1.2PF,50V,B,C0G,0402,TR; signal model: C2_6010B0077201_1_2pF_50V_2; room: Sheet10
C6742 = CSC0402: part number: CSC0402-1UF_6.3V_2,6010B0006001,CSC_100X050X040_2,0.55MM,CSC0402,0402,X5R,CAP-CHIP,1UF,6.3V,K,X5R,0402,TR; signal model: C2_6010B0006001_1uF_6_3V_2; room: Sheet10
C6743 = CSC0603: part number: CSC0603-2.2UF_6.3V_3,6010B0027401,CSC_160X080X090_2,1.05MM,CSC0603,0603,X5R,CAPACITOR-CHIP,2.2UF,6.3V,K,X5R,0603,TR; signal model: C2_6010B0027401_2_2uF_6_3V_3; room: Sheet10
C6745 = CSC0402: part number: CSC0402-470PF_50V_2,6010A0025101,CSC_100X050X040_2,0.55MM,CSC0402,0402,X7R,CAP-CHIP-471-K,50V-X7R-0402-TAP; signal model: C2_6010A0025101_470pF_50V_2; room: Sheet10
C6746 C6747 = CSC0402: part number: CSC0402-0.01UF_50V_2,6010B0058401,CSC_100X050X040_2,0.55MM,CSC0402,0402,X7R,CAP-CHIP,0.01UF,50V,K,X7R,0402,TAP; signal model: C2_6010B0058401_0_01uF_50V_2; room: Sheet10
C6749 = CSC0402: part number: CSC0402-2200PF_50V_2,6010A0036305,CSC_100X050X040_2,0.55MM,CSC0402,0402,X7R,CAP-CHIP-2200PF-50V-K-X7R-0402-TAP; signal model: C2_6010A0036305_2200pF_50V_2; room: Sheet10
C7000 C7002 C60610-C60612 C60910-C60912 C61010 C61110 C61700 C61710 = CSC0603: part number: CSC0603-10UF_6.3V_3,6010B0044901,CSC_160X080X080_2,0.95MM,CSC0603,0603,X5R,CAP-CHIP,10UF,6.3V,M,X5R,0603,TR; signal model: C2_6010B0044901_10uF_6_3V_3; room: Sheet12
C7001 C7003 C60600-C60604 C60901 C61000 C61100 = CSC0805: part number: CSC0805-22UF_6.3V_5,6010A0040702,CSC_200X125X130_2,1.45MM,CSC0805,0805,X5R,CAP-CHIP-22UF-6.3V-M-X5R-0805-TAP; signal model: C2_6010A0040702_22uF_6_3V_5; room: Sheet12
C7100 = CSC0402: part number: CSC0402-220PF_50V_2,6010B0076701,CSC_100X050X040_2,0.55MM,CSC0402,0402,C0G,CAP-CHIP,220PF,50V,J,C0G,0402,TR; signal model: C2_6010B0076701_220pF_50V_2; room: Sheet14
C7101 C7109 = CSC0402: part number: CSC0402-33PF_50V_2,6010A0028901,CSC_100X050X040_2,0.56MM,CSC0402,0402,,CAP-CHIP-33PF-J,50V-TAP(0402); signal model: C2_6010A0028901_33pF_50V_2; room: Sheet14
C7102 = CSC0805: part number: CSC0805-10UF_6.3V_5,6010A0032901,CSC_200X125X130_2,1.45MM,CSC0805,0805,X5R,CAP-CHIP-106-K,6.3V-X5R-0805-TAP; signal model: C2_6010A0032901_10uF_6_3V_5; room: Sheet14
C7104 C7108 C7121 = CSC0603: part number: CSC0603-10UF_6.3V_3,6010B0044901,CSC_160X080X080_2,0.95MM,CSC0603,0603,X5R,CAP-CHIP,10UF,6.3V,M,X5R,0603,TR; signal model: C2_6010B0044901_10uF_6_3V_3; room: Sheet14
C7110 C7114 C7120 C7123 = CSC0402: part number: CSC0402-1UF_10V_2,6010B0055001,CSC_100X050X040_2,0.55MM,CSC0402,0402,X5R,CAP-CHIP,1UF,10V,K,X5R,0402,TR; signal model: C2_6010B0055001_1uF_10V_2; room: Sheet14
C7122 = CSC0402: part number: CSC0402-680PF_50V_2,6010A0025501,CSC_100X050X040_2,0.55MM,CSC0402,0402,X7R,CAP-CHIP-681-K,50V-X7R-0402-TAP; signal model: C2_6010A0025501_680pF_50V_2; room: Sheet14
C7203 C7205 = CSC0402: part number: CSC0402-0.1UF_16V_2_DY,6010A0036403_DY,CSC_100X050X040_2,0.55MM,CSC0402,0402,X7R,CAP-CHIP,0.1UF,16V,K,X7R,0402,TAP; signal model: C2_6010A0036403_DY_0_1uF_16V_2_DY; room: Sheet13
C7206 = CSC0402: part number: CSC0402-0.1UF_16V_2,6010A0036403,CSC_100X050X040_2,0.55MM,CSC0402,0402,X7R,CAP-CHIP,0.1UF,16V,K,X7R,0402,TAP; signal model: C2_6010A0036403_0_1uF_16V_2; room: Sheet13
C7207 C7225 = CSC0402: part number: CSC0402-CSC0402_DY,CSC0402_DY,CSC_100X050X040_2,0.55MM,CSC0402,0402,,CSC0402_OPEN; signal model: C2_CSC0402_DY_CSC0402_DY; room: Sheet13
C7510-C7513 C7541 C7546 C7577 = CSC0402: part number: CSC0402-0.1UF_25V_2,6010B0087101,CSC_100X050X040_2,0.55MM,CSC0402,0402,X5R,CAP-CHIP,0.1UF,25V,K,X5R,0402,TR; signal model: C2_6010B0087101_0_1uF_25V_2; room: Sheet46
C7514-C7522 C7526 C7527 C7551 C7552 C7566-C7569 C7572-C7574 C7591 C7593 = CSC0402: part number: CSC0402-0.1UF_16V_2,6010A0036403,CSC_100X050X040_2,0.55MM,CSC0402,0402,X7R,CAP-CHIP,0.1UF,16V,K,X7R,0402,TAP; signal model: C2_6010A0036403_0_1uF_16V_2; room: Sheet46
C7528 C7529 C7531-C7534 = CSC0402: part number: CSC0402-18PF_50V_2,6010A0036105,CSC_100X050X040_2,0.55MM,CSC0402,0402,NPO,CAP-CHIP-18PF-50V-J-NPO-0402-TAP; signal model: C2_6010A0036105_18pF_50V_2; room: Sheet31
C7535-C7540 = CSC0402: part number: CSC0402-18PF_50V_2,6010A0036105,CSC_100X050X040_2,0.55MM,CSC0402,0402,NPO,CAP-CHIP-18PF-50V-J-NPO-0402-TAP; signal model: C2_6010A0036105_18pF_50V_2; room: Sheet32
C7578 C7580 C7583-C7585 C7979 = CSC0402: part number: CSC0402-1000PF_50V_2,6010071020AT,CSC_100X050X055_2,0.7MM,CSC0402,0402,X7R,CAPACITOR-CHIP,1000PF,50V,K,X7R,0402,TR; signal model: C2_6010071020AT_1000PF_50V_2; room: Sheet46
C7600 = CSC0402: part number: CSC0402-2200PF_50V_2,6010A0036305,CSC_100X050X040_2,0.55MM,CSC0402,0402,X7R,CAP-CHIP-2200PF-50V-K-X7R-0402-TAP; signal model: C2_6010A0036305_2200pF_50V_2; room: Sheet5
C7602 = CSC0402: part number: CSC0402-10PF_50V_2,6010A0025401,CSC_100X050X040_2,0.55MM,CSC0402,0402,NPO,CAP-CHIP-10PF-D,50V-NPO-0402-TAP; signal model: C2_6010A0025401_10pF_50V_2; room: Sheet5
C7661 = CSC0402: part number: CSC0402-CSC0402_DY,CSC0402_DY,CSC_100X050X040_2,0.55MM,CSC0402,0402,,CSC0402_OPEN; signal model: C2_CSC0402_DY_CSC0402_DY; room: Sheet9
C7761 = CSC0402: part number: CSC0402-CSC0402_DY,CSC0402_DY,CSC_100X050X040_2,0.55MM,CSC0402,0402,,CSC0402_OPEN; signal model: C2_CSC0402_DY_CSC0402_DY; room: Sheet11
C9100 C9101 = CSC0402: part number: CSC0402-1UF_6.3V_2,6010B0006001,CSC_100X050X040_2,0.55MM,CSC0402,0402,X5R,CAP-CHIP,1UF,6.3V,K,X5R,0402,TR; signal model: C2_6010B0006001_1uF_6_3V_2; room: Sheet48
C9102 = CSC0402: part number: CSC0402-1000PF_50V_2_DY,6010071020AT_DY,CSC_100X050X055_2,0.7MM,CSC0402,0402,X7R,CAPACITOR-CHIP,1000PF,50V,K,X7R,0402,TR; signal model: C2_6010071020AT_DY_1000PF_50V_2_DY; room: Sheet48
C9150 = CSC0402: part number: CSC0402-1000PF_50V_2,6010071020AT,CSC_100X050X055_2,0.7MM,CSC0402,0402,X7R,CAPACITOR-CHIP,1000PF,50V,K,X7R,0402,TR; signal model: C2_6010071020AT_1000PF_50V_2; room: Sheet48
C60013 = CSC0603: part number: CSC0603-0.1UF_25V_3,6010A0057701,CSC_160X080X080_2,0.95MM,CSC0603,0603,X7R,CAP-CHIP,0.1UF,25V,K,X7R,0603,TR; signal model: C2_6010A0057701_0_1uF_25V_3; room: Sheet13
C60209 = CSC0402: part number: CSC0402-1UF_6.3V_2,6010B0006001,CSC_100X050X040_2,0.55MM,CSC0402,0402,X5R,CAP-CHIP,1UF,6.3V,K,X5R,0402,TR; signal model: C2_6010B0006001_1uF_6_3V_2; room: Sheet12
C60300-C60302 = CSC0805: part number: CSC0805-22UF_6.3V_5,6010A0040702,CSC_200X125X130_2,1.45MM,CSC0805,0805,X5R,CAP-CHIP-22UF-6.3V-M-X5R-0805-TAP; signal model: C2_6010A0040702_22uF_6_3V_5; room: Sheet7
C60303 = CSC0805: part number: CSC0805-22UF_6.3V_5_DY,6010A0040702_DY,CSC_200X125X130_2,1.45MM,CSC0805,0805,X5R,CAP-CHIP-22UF-6.3V-M-X5R-0805-TAP; signal model: C2_6010A0040702_DY_22uF_6_3V_5_DY; room: Sheet7
C60304 = CSC0402: part number: CSC0402-0.022UF_16V_2_DY,6010A0000101_DY,CSC_100X050X040_2,0.55MM,CSC0402,0402,X7R,CAP-CHIP-223-K,16V-X7R-0402-TAP; signal model: C2_6010A0000101_DY_0_022uF_16V_2_DY; room: Sheet7
C60306 = CSC0402: part number: CSC0402-1UF_6.3V_2,6010B0006001,CSC_100X050X040_2,0.55MM,CSC0402,0402,X5R,CAP-CHIP,1UF,6.3V,K,X5R,0402,TR; signal model: C2_6010B0006001_1uF_6_3V_2; room: Sheet7
C60310 = CSC0805: part number: CSC0805-10UF_25V_5,6010B0150801,CSC_200X125X140_2,1.55MM,CSC0805,0805,X5R,CAP-CHIP,10UF,25V,K,X5R,0805,TR,1.25MM; signal model: C2_6010B0150801_10UF_25V_5; room: Sheet7
C60311 = CSC0805: part number: CSC0805-10UF_25V_5_DY,6010B0150801_DY,CSC_200X125X140_2,1.55MM,CSC0805,0805,X5R,CAP-CHIP,10UF,25V,K,X5R,0805,TR,1.25MM; signal model: C2_6010B0150801_10UF_25V_5_DY; room: Sheet7
C60315 C60351 = CSC0402: part number: CSC0402-0.1UF_16V_2,6010A0036403,CSC_100X050X040_2,0.55MM,CSC0402,0402,X7R,CAP-CHIP,0.1UF,16V,K,X7R,0402,TAP; signal model: C2_6010A0036403_0_1uF_16V_2; room: Sheet7
C60316 = CSC0402: part number: CSC0402-CSC0402_DY,CSC0402_DY,CSC_100X050X040_2,0.55MM,CSC0402,0402,,CSC0402_OPEN; signal model: C2_CSC0402_DY_CSC0402_DY; room: Sheet7
C60350 = CSC0603: part number: CSC0603-10UF_6.3V_3,6010B0044901,CSC_160X080X080_2,0.95MM,CSC0603,0603,X5R,CAP-CHIP,10UF,6.3V,M,X5R,0603,TR; signal model: C2_6010B0044901_10uF_6_3V_3; room: Sheet7
C60900 = CAP_AL_SP: part number: CAP_AL_SP-470UF_2V,6010B0107301,CS_730X430X190_2,2.05MM,CAP_AL_SP,,,CAPACITOR-AL-SP,470UF,2V,M,105C,DX1.9,SMD,TR,4.5MOHM; signal model: C2_6010B0107301_470uF_2V; room: Sheet12
CN245 = CN_10_2G: part number: CN_10_2G-ACES_50503_0104N_001_10P,6012B0245904,FPC_ACES_10_100_R_200_3,2.25MM,,CONNECTOR,FPC,2.0MM,FL,1X10,1.0MM,90D,SMD,TR,THERMOPLASTIC,MATT TIN,100U; room: Sheet16
CN251 = 50503_0244N_001: part number: 50503_0244N_001-ACES_50503_0244N_001_24P,6012B0245909,FPC_ACES_24_100_R_200_4,2.15MM,,CONNECTOR,FPC,FL,BLK,1X24,1.0MM,90D,SMD,TR,THERMOPLASTIC,MATT; room: Sheet16
CN281 = 50503_0084N_001: part number: 50503_0084N_001-ACES_50503_0084N_001_8P,6012B0245912,FPC_ACES_8_100_R_200_4,2.25MM,,CONNECTOR,FPC,H EQUAL 2.0MM,FL,1X8,1.0MM,90D,SMD,TR,MATT TIN; room: Sheet16
CN600 = CN_04_2G: part number: CN_04_2G-LCN_AWM10_0429980_0004_4P,6012B0615101,WTB_LCN_4_100_SMD_R_M_290,3.1MM,,CONNECTOR,W TO B,ML,NTU,1X4,1.00MM,90D,SMD,TR; room: Sheet19
CN901 = PSDATG_11GLBS1NN4H1: part number: PSDATG_11GLBS1NN4H1-TAITWUN_PSDATG_11GLBS1NN4H1_11P,6026B0324901,SD_TAIT_11_SMD_ST_285_2,3.30MM,,TAI_TWUN_PSDATG_11GLBS1NN4H1_11P; room: Sheet20
CN1300 = APCI0062_P001A: part number: APCI0062_P001A-LOTES_APCI0062-P001A_NGFF_E_KEY_75P,6026B0276201,MPCI_LOTES_75_050_RV_198,2.13MM,,SOCKET,PCIEX KEY E NGFF,75P,0.5MM,GOLD FLASH,20D,SMD,TR; room: Sheet21
CN2002 = 50505_0044N_002: part number: 50505_0044N_002-ACER_50505_0044N_002_4P,6012B0317703,FPC_ACES_4_100_R_150,1.85MM,,CONNECTOR,FPC,1.5MM,FL,1X4,1.0MM,90D,SMD,TR,MATT TIN,100U; room: Sheet22
CN2003 = 50505_0044N_002: part number: 50505_0044N_002-ACER_50505_0044N_002_4P,6012B0317703,FPC_ACES_4_100_R_150,1.85MM,,CONNECTOR,FPC,1.5MM,FL,1X4,1.0MM,90D,SMD,TR,MATT TIN,100U; room: Sheet47
CN2401 = CN_09_4G_USB30: part number: CN_09_4G_USB30-ALLTOP_C107MK_9093D_L_9P,6012B0700401,USB3_OTOP_9_DIP_RV_S_100_186,2.26MM,,CONNECTOR,USB 3.0,-1.0/1.86MM,FL,BLU,9P,90D,DIP,TR,G/F; room: Sheet23
CN2403 = 020173GR004M59GZL: part number: 020173GR004M59GZL-SUYIN_020173GR004M59GZL_4P,6012B0387801,USB_SYN_4_RS_S_110_250,2.5MM,,CONNECTOR,USB,A TYPE,3.36/6.22MM,FL,1X4,90D,DIP,TR,HI TEMP PLASTIC,GOLD,30U; room: Sheet47
CN3000 = 50203_03001_001: part number: 50203_03001_001-ACES_50203_03001_001_30P,6012B0431201,WTB_ACES_30_050_SMD_R_F_265_1,2.8MM,,CONNECTOR,W TO B,FL,1X30,0.5MM,90D,SMD,TR; room: Sheet26
CN3150 = 099A4AC19HBLBNF: part number: 099A4AC19HBLBNF-CONCRAFT_099A4AC19HBLBNF_19P,6012B0492301,HDMI_CONFT_19_RS_060_218,2.33MM,,CONNECTOR,HDMI,-3.37/2.18MM,ML,BLK,19P,90D,DIP,TR,GOLD,3U; room: Sheet27
CN6000 = CN_05_2G: part number: CN_05_2G-HR_A1255WR_S_05PNLNT1TS1R_5P,6012B0721301,BTB_JOINT_5_125_M_215,2.3MM,,CONNECTOR,1.25MM PITCH; room: Sheet5
CN6050 = CN_09: part number: CN_09-ACES_50299_00901_001_9P,6012B0131110-001,HL10BM-6012B0131110-001,3.15MM,,CONNECTOR,W TO B,SMD,G/F; room: Sheet5
CN9100 = CN_10_2G: part number: CN_10_2G-ACES_50503_0104N_001_10P,6012B0245904,FPC_ACES_10_100_R_200_3,2.25MM,,CONNECTOR,FPC,2.0MM,FL,1X10,1.0MM,90D,SMD,TR,THERMOPLASTIC,MATT TIN,100U; room: Sheet48
D250-D257 = SFI0402ML120C_LF: part number: SFI0402ML120C_LF-SFI_SFI0402ML120C_LF_SMD_2P,6011B0130001,DS_100X050X060_2_S2,0.75MM,,DIODE,TVS,12V,10A,SMD,TR; room: Sheet16
D280 D281 = PESD5V2S2UT: part number: PESD5V2S2UT-LITEON_L30ESDXVC3_2_DSOT23_3P,6011B0136901,DSOT23_290X130X150_3_095,1.65MM,DIODE,ESD,5V,17A,300W,SMD,SOT23,TR; room: Sheet16
D282 = SFI0402ML120C_LF: part number: SFI0402ML120C_LF-SFI_SFI0402ML120C_LF_SMD_2P_DY,6011B0130001_DY,DS_100X050X060_2_S2,0.75MM,,DIODE,TVS,12V,10A,SMD,TR; room: Sheet16
D500 = PESD5V2S2UT: part number: PESD5V2S2UT-LITEON_L30ESDXVC3_2_DSOT23_3P,6011B0136901,DSOT23_290X130X150_3_095,1.65MM,DIODE,ESD,5V,17A,300W,SMD,SOT23,TR; room: Sheet15
D501 = AZ2015_01H: part number: AZ2015_01H-AMC_AZ2015_01H_SOD523_2P_DY,6011B0082901_DY,DSSOD523_120X080X070_2_150,0.85MM,,DIODE,ESD,6V,8.5A,SMD,SOD523,TR; room: Sheet18
D600 = PESD5V2S2UT: part number: PESD5V2S2UT-LITEON_L30ESDXVC3_2_DSOT23_3P_DY,6011B0136901_DY,DSOT23_290X130X150_3_095,1.65MM,DIODE,ESD,5V,17A,300W,SMD,SOT23,TR; room: Sheet19
D901 D902 = SFI0402ML120C_LF: part number: SFI0402ML120C_LF-SFI_SFI0402ML120C_LF_SMD_2P_DY,6011B0130001_DY,DS_100X050X060_2_S2,0.75MM,,DIODE,TVS,12V,10A,SMD,TR; room: Sheet20
D2406 = AZ1045_04F_R7G: part number: AZ1045_04F_R7G-AMAZING_AZ1045_04F_R7G_10P,6011B0172501,DS_250X100X065_10_050,0.8MM,,DIODE-ESD,12V,0.5PF,15K/10K,DFN2510P10E,SMD,TR; signal model: D10_6011B0172501_AMAZING_AZ1045_04F_R7G_10P; room: Sheet23
D2409 = AZC099_04S_R7G: part number: AZC099_04S_R7G-AMC_AZC099_04S_R7G_SOT23_6P,6011B0158001,DSSOT23_290X160X145_6_095,1.6MM,,IC,ESD PROTECTION,SOT23,6P,TR; room: Sheet23
D2410 = AZC099_04S_R7G: part number: AZC099_04S_R7G-AMC_AZC099_04S_R7G_SOT23_6P,6011B0158001,DSSOT23_290X160X145_6_095,1.6MM,,IC,ESD PROTECTION,SOT23,6P,TR; room: Sheet47
D3000 = AZC099_04S_R7G: part number: AZC099_04S_R7G-AMC_AZC099_04S_R7G_SOT23_6P,6011B0158001,DSSOT23_290X160X145_6_095,1.6MM,,IC,ESD PROTECTION,SOT23,6P,TR; room: Sheet26
D3950 D3951 = SFI0402ML120C_LF: part number: SFI0402ML120C_LF-SFI_SFI0402_050E050PP_LF_SMD_2P,6011B0175401,DS_100X050X060_2_S2,0.75MM,,DIODE,VARISTOR,3.3V,1MA,20W,SMD,TR; room: Sheet24
D4500 = SFI0603_240E2R5PP_LF: part number: SFI0603_240E2R5PP_LF-SFI_SFI0603_240E2R5PP_LF_2P_DY,6011B0096201_DY,DS_160X080X090_2,1.05MM,,DIODE,ESD,24V,SMD,0603,TR; room: Sheet41
D4501 = SCH_SINGLE_B: part number: SCH_SINGLE_B-DIODE-BAT54-TAP-PHP,60110GA0367T,DSSOT23_292X130X109_3_095,1.24MM,SCH_SINGLE_B,DIODE-BAT54-TAP-PHP; room: Sheet40
D4700 D4701 = SCH_SINGLE_B: part number: SCH_SINGLE_B-DIODE-BAT54-TAP-PHP,60110GA0367T,DSSOT23_292X130X109_3_095,1.24MM,SCH_SINGLE_B,DIODE-BAT54-TAP-PHP; room: Sheet45
D6000 D6001 = SCH_DUAL_2IN_1OUT_A: part number: SCH_DUAL_2IN_1OUT_A-BAT54C_30V_0.2A,6011A0026803,TSMI_3B,1.25MM,SCH_DUAL_2IN_1OUT_A,,,DIODE-DUAL-SCH-30V-200MA-200MW-5NS-SMD-SOT23-TR; room: Sheet5
D7000 = SCH_SINGLE_B: part number: SCH_SINGLE_B-DIODE-BAT54-TAP-PHP,60110GA0367T,DSSOT23_292X130X109_3_095,1.24MM,SCH_SINGLE_B,DIODE-BAT54-TAP-PHP; room: Sheet13
D7152 = SFI0402ML120C_LF: part number: SFI0402ML120C_LF-SFI_SFI0402ML120C_LF_SMD_2P,6011B0130001,DS_100X050X060_2_S2,0.75MM,,DIODE,TVS,12V,10A,SMD,TR; room: Sheet27
D7200 = SCH_SINGLE_B: part number: SCH_SINGLE_B-BAT54_30V_0.2A_DY,6011A0026801_DY,TSOT23_290X130X110_3_096_P1,1.25MM,SCH_SINGLE_B,DIODE-SCH-30V-200MA-200MW-5NS-SMD-SOT23-TR; room: Sheet13
D7501 D7503 = VARISTOR: part number: VARISTOR-SFI0402_050E3R0PP_LF,6011B0161301,DS_100X050X060_2_S2,0.75MM,VARISTOR,DIODE,VARISTOR,60V,1A,SMD,TR; room: Sheet17
D9100 = PESD5V2S2UT: part number: PESD5V2S2UT-LITEON_L30ESDXVC3_2_DSOT23_3P,6011B0136901,DSOT23_290X130X150_3_095,1.65MM,DIODE,ESD,5V,17A,300W,SMD,SOT23,TR; room: Sheet48
D9128 D9129 = 19_223_S2T1D_C30_2T: part number: 19_223_S2T1D_C30_2T-EVL_19_223_S2T1D_C30_2T_4P,6011B0110001,LED_EVERLI_V_D_160X150X060,0.75MM,,DIODE-LED,YEL/WHT,1615,72/112MCD,140D,50/25MA,SMD,4P,TR; room: Sheet48
D9150 = SFI0402ML120C_LF: part number: SFI0402ML120C_LF-SFI_SFI0402ML120C_LF_SMD_2P_DY,6011B0130001_DY,DS_100X050X060_2_S2,0.75MM,,DIODE,TVS,12V,10A,SMD,TR; room: Sheet48
D60000 = SCH_SINGLE_B: part number: SCH_SINGLE_B-DIODE-BAT54-TAP-PHP,60110GA0367T,DSSOT23_292X130X109_3_095,1.24MM,SCH_SINGLE_B,DIODE-BAT54-TAP-PHP; room: Sheet12
D60002 = SCH_DUAL_2IN_1OUT_A: part number: SCH_DUAL_2IN_1OUT_A-BAT54C_30V_0.2A,6011A0026803,TSMI_3B,1.25MM,SCH_DUAL_2IN_1OUT_A,,,DIODE-DUAL-SCH-30V-200MA-200MW-5NS-SMD-SOT23-TR; room: Sheet13
D60003 = D_DUAL_SERIES_A: part number: D_DUAL_SERIES_A-BAV99,60110GA0450T,DSSOT23_290X130X110_3_095-2,1.25MM,D_DUAL_SERIES_A,DIODE-BAV99-3P-SOT23-TAP-PHP CPQ; room: Sheet13
FIX1-FIX8 = FIX_MASK: part number: FIX_MASK-FIX_MASK,FIX_MASK,FIX_MASK,0.127MM,FIX_MASK,FIX_MASK; room: Sheet15
FIX23-FIX26 = FIX_MASK: part number: FIX_MASK-FIX_MASK,FIX_MASK,FIX_MASK,0.127MM,FIX_MASK,FIX_MASK; room: Sheet47
FIX9113-FIX9116 = FIX_MASK: part number: FIX_MASK-FIX_MASK,FIX_MASK,FIX_MASK,0.127MM,FIX_MASK,FIX_MASK; room: Sheet48
FUSE3004 = FUSE: part number: FUSE-1A_32V,6036B0086701,FUSE_160X080X031_2,0.455MM,FUSE,FUSE,FR4,1A,32V,SMD,1.6X0.8,TR; room: Sheet26
JACK600 = 2SJ3095_078111F: part number: 2SJ3095_078111F-SINGA_2SJ3095_078111F_6P,6026B0343301,AUDIO_SIGAT_6_R_165_165,1.85MM,,CONNECTOR_AUDIO JACK_2SJ3095_078111F; room: Sheet19
L300 = BEAD_SINGLE: part number: BEAD_SINGLE-FBM_11_160808_121T,60140EA0319T,EMIS_BLM11,1MM,BEAD_SINGLE,,,,BEAD,120OHM,25%,200MA,0.2OHM,0603INCH,10; signal model: L2_60140EA0319T_FBM_11_160808_121T; room: Sheet17
L2404 = CHOKE_4PIN_C: part number: CHOKE_4PIN_C-MCF12102G900-T,6014B0247601-001,CAESAR-6014B0247601-001,0.8MM,CHOKE_4PIN_C,CHOKE,90OHM,25%,100MA,185X70X190,0.25OHM,100MHZ,4P,TR; signal model: L4_6014B0247601-001_MCF12102G900-T; room: Sheet23
L2406 = CHOKE_4PIN_C: part number: CHOKE_4PIN_C-MCF12102G900-T,6014B0247601-001,CAESAR-6014B0247601-001,0.8MM,CHOKE_4PIN_C,CHOKE,90OHM,25%,100MA,185X70X190,0.25OHM,100MHZ,4P,TR; signal model: L4_6014B0247601-001_MCF12102G900-T; room: Sheet47
L2432 L2440 = CHOKE_4PIN_C: part number: CHOKE_4PIN_C-WCM_2012SHS_850T,6014B0219101,LS_200X120X140_4_080,1.55MM,CHOKE_4PIN_C,CHOKE,85OHM,25%,400MA,0805,0.3OHM,100MHZ; signal model: L4_6014B0219101_WCM_2012SHS_850T; room: Sheet23
L6000 = POWER_INDUCTOR: part number: POWER_INDUCTOR-PCMB061H_4R7MS,6014B0090301,LS_660X660X180_2_570,1.95MM,,INDUCTOR,4.7UH,20%,100KHZ,3.5A,7.4X6.6X1.8MM,SMD,TR; room: Sheet5
L6100 = POWER_INDUCTOR: part number: POWER_INDUCTOR-PCMB061H-2R2MS,6014B0090401,LS_660X660X180_2_540,1.95MM,,INDUCTOR,2.2UH,20%,100KHZ,6A,7.4X6.6X1.8MM,SMD,TR; room: Sheet6
L6150 = CHOKE_2PIN: part number: CHOKE_2PIN-PCMB061H-1R0MS,6014B0138201,LS_660X660X180_2_605,1.95MM,CHOKE_2PIN,,,,INDUCTOR,1.0UH,20%,100KHZ,7A,7.05X6.6X1.6MM,SMD,TR; signal model: L2_6014B0138201_PCMB061H-1R0MS; room: Sheet6
L6610 = IDUT_4PIN: part number: IDUT_4PIN-PCMB061H-R33MS,6014B0257601,LS_660X660X180_4,1.95MM,IDUT_4PIN,,,,INDUCTOR,0.33UH,+/- 20%,100KHZ,22A,6.6*7.4*1.8MM,SMD,TR; signal model: L4_6014B0257601_PCMB061H-R33MS; room: Sheet9
L6710 = IDUT_4PIN: part number: IDUT_4PIN-PCMB061H-R33MS,6014B0257601,LS_660X660X180_4,1.95MM,IDUT_4PIN,,,,INDUCTOR,0.33UH,+/- 20%,100KHZ,22A,6.6*7.4*1.8MM,SMD,TR; signal model: L4_6014B0257601_PCMB061H-R33MS; room: Sheet11
L7600 L7601 = BEAD_SINGLE: part number: BEAD_SINGLE-KC_FBMA_11_321611_121A60T,6014B0114801,LS_320X160X130_2,1.45MM,BEAD_SINGLE,,,,KC_FBMA_11_321611_121A60T_2P; signal model: L2_6014B0114801_KC_FBMA_11_321611_121A60T; room: Sheet5
L60300 = CHOKE_2PIN: part number: CHOKE_2PIN-PCMB061H-1R0MS,6014B0138201,LS_660X660X180_2_605,1.95MM,CHOKE_2PIN,,,,INDUCTOR,1.0UH,20%,100KHZ,7A,7.05X6.6X1.6MM,SMD,TR; signal model: L2_6014B0138201_PCMB061H-1R0MS; room: Sheet7
L60600 = IDUT_SINGLE: part number: IDUT_SINGLE-NRS5020T1R0N,6014B0186903,LS_500X500X200_2_340_P2,2.1MM,IDUT_SINGLE,,,,INDUCTOR,1.0UH,30%,100KHZ,3.5A,4.9X4.9X2MM,SMD,TR; signal model: L2_6014B0186903_NRS5020T1R0N; room: Sheet12
L60900 = IDUT_SINGLE: part number: IDUT_SINGLE-PCMB061H_R47MS,6014B0162301,LS_660X660X180_2_605,1.95MM,IDUT_SINGLE,,,,INDUCTOR,0.47UH,20%,100KHZ,11A,7.05X6.6X1.6MM,SMD,TR; signal model: L2_6014B0162301_PCMB061H_R47MS; room: Sheet12
PAD319 = POWERPAD_2: part number: POWERPAD_2-POWERPAD1X1M,POWERPAD1X1M,POWERPAD1X1M,0.559MM,POWERPAD_2,POWERPAD1X1M; room: Sheet17
PAD500-PAD503 = POWERPAD_2: part number: POWERPAD_2-POWERPAD1X1M,POWERPAD1X1M,POWERPAD1X1M,0.559MM,POWERPAD_2,POWERPAD1X1M; room: Sheet18
PAD2000 = POWERPAD_2: part number: POWERPAD_2-POWERPAD_2_0610,POWERPAD_2_0610,POWERPAD_2_0610,0.559MM,POWERPAD_2,POWERPAD_2_0610; room: Sheet22
PAD3003 = POWERPAD_2: part number: POWERPAD_2-POWERPAD1X1M,POWERPAD1X1M,POWERPAD1X1M,0.559MM,POWERPAD_2,POWERPAD1X1M; room: Sheet26
PAD4501 = POWERPAD_2: part number: POWERPAD_2-POWERPAD2X2M_DY,POWERPAD2X2M_DY,POWERPAD2X2M_NP,0.559MM,POWERPAD_2,POWERPAD2X2M; room: Sheet40
PAD6100 PAD6110 PAD6150 PAD6160 = POWERPAD_2: part number: POWERPAD_2-POWERPAD_2_0610,POWERPAD_2_0610,POWERPAD_2_0610,0.559MM,POWERPAD_2,POWERPAD_2_0610; room: Sheet6
PAD6121 = POWERPAD_2: part number: POWERPAD_2-POWERPAD1X1M,POWERPAD1X1M,POWERPAD1X1M,0.559MM,POWERPAD_2,POWERPAD1X1M; room: Sheet6
PAD6610 = POWERPAD_2: part number: POWERPAD_2-POWERPAD_2_0610,POWERPAD_2_0610,POWERPAD_2_0610,0.559MM,POWERPAD_2,POWERPAD_2_0610; room: Sheet9
PAD6710 = POWERPAD_2: part number: POWERPAD_2-POWERPAD_2_0610,POWERPAD_2_0610,POWERPAD_2_0610,0.559MM,POWERPAD_2,POWERPAD_2_0610; room: Sheet11
